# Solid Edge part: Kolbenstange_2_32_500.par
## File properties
Username: ahadarics
Dokumentum tartalom típus: 0
Author: ahadarics
Last saved by: ahadarics
Revision: 89
Sűrűség: 0,000 kg/m^3
Pontosság: 0,990
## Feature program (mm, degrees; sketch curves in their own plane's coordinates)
base feature "unnamed BaseFeature 1"
thread "unnamed Thread 1"
chamfer "Letörés_1"  SetBackValue2 = 20 deg
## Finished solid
Body 1: solid body, 19 faces, 31 edges, 16 vertices.
  Faces by surface: plane 8, cylinder 5, cone 3, torus 3
  Edges by curve: circle 18, line 8, curve on surface 3, ellipse 2
Bounding box of the edges (mm; curved faces can reach further): 32.000 x 32.000 x 575.500, from (-16, -16, -50.25) to (16, 16, 525.25).
Cylindrical faces by radius (mm): R3.95 x1, R5 x1, R5.8 x1, R6 x1, R16 x1
Conical faces (half-angle, radius in mm at the cone's reference point): 20 deg R3.9991 x1, 30 deg R5.9 x1, 60 deg R4.475 x1
Toroidal faces (ring radius, tube radius in mm): R4.35 r0.4 x2, R4.6 r1.2 x1
Planar faces by outward normal: +x 1, +z 3, -x 1, -z 1, oblique 2
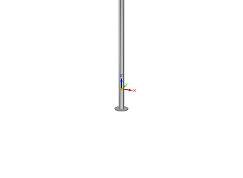
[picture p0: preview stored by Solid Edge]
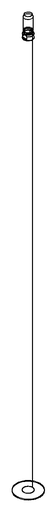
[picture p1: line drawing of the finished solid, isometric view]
